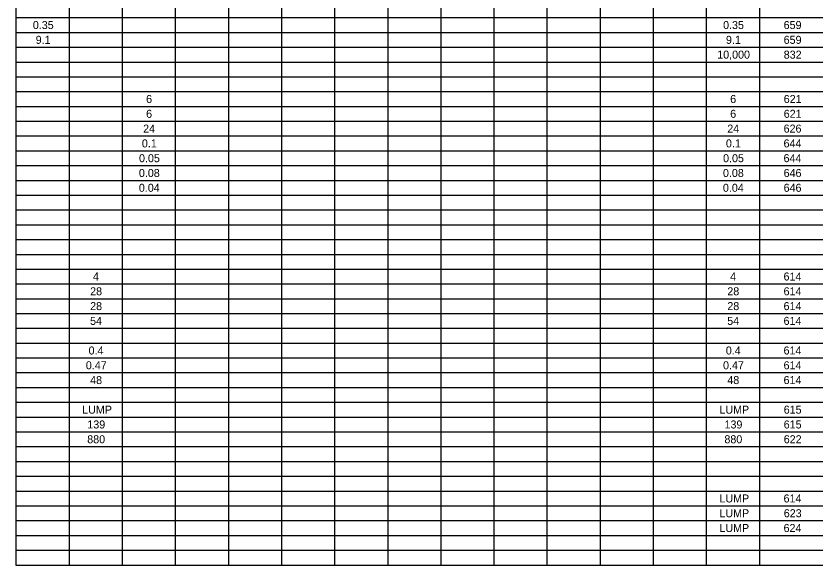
# Model space of a CAD drawing. Extents: x -98 to 34, y 0 to 58.
# Drawn here: x -97.69 to -82.55, y 36.85 to 47.24 of the extents above; entities that cross this region are included whole.
import ezdxf

# ---------------------------------------------------------------- set-up
doc = ezdxf.new("R2010")
doc.units = 0
doc.layers.add('Default', color=7, linetype='Continuous')

msp = doc.modelspace()

# ---------------------------------------------------------------- linework, layer by layer
at = {"layer": 'Default'}
for p, q in [((-97.686, 57.846), (-97.686, 36.848)), ((-84.626, 57.846), (-84.626, 36.848)), ((-83.621, 57.846), (-83.621, 36.848)), ((-96.681, 57.286), (-96.681, 36.848)), ((-95.676, 57.286), (-95.676, 36.848)), ((-94.672, 57.286), (-94.672, 36.848)), ((-93.667, 57.286), (-93.667, 36.848)), ((-92.663, 57.286), (-92.663, 36.848)), ((-91.658, 57.286), (-91.658, 36.848)), ((-90.653, 57.286), (-90.653, 36.848)), ((-89.649, 57.286), (-89.649, 36.848)), ((-88.644, 57.286), (-88.644, 36.848)), ((-87.64, 57.286), (-87.64, 36.848)), ((-86.635, 57.286), (-86.635, 36.848)), ((-85.63, 57.286), (-85.63, 36.848)), ((-97.686, 47.207), (-67.186, 47.207)), ((-97.686, 46.927), (-67.186, 46.927)), ((-97.686, 46.647), (-67.186, 46.647)), ((-97.686, 46.367), (-67.186, 46.367)), ((-97.686, 46.087), (-67.186, 46.087)), ((-97.686, 45.807), (-67.186, 45.807)), ((-97.686, 45.527), (-67.186, 45.527)), ((-97.686, 45.247), (-67.186, 45.247)), ((-97.686, 44.967), (-67.186, 44.967)), ((-97.686, 44.687), (-67.186, 44.687)), ((-97.686, 44.407), (-67.186, 44.407)), ((-97.686, 44.127), (-67.186, 44.127)), ((-97.686, 43.847), (-67.186, 43.847)), ((-97.686, 43.567), (-67.186, 43.567)), ((-97.686, 43.287), (-67.186, 43.287)), ((-97.686, 43.007), (-67.186, 43.007)), ((-97.686, 42.727), (-67.186, 42.727)), ((-97.686, 42.447), (-67.186, 42.447)), ((-97.686, 42.167), (-67.186, 42.167)), ((-97.686, 41.887), (-67.186, 41.887)), ((-97.686, 41.607), (-67.186, 41.607)), ((-97.686, 41.327), (-67.186, 41.327)), ((-97.686, 41.048), (-67.186, 41.048)), ((-97.686, 40.768), (-67.186, 40.768)), ((-97.686, 40.488), (-67.186, 40.488)), ((-97.686, 40.208), (-67.186, 40.208)), ((-97.686, 39.928), (-67.186, 39.928)), ((-97.686, 39.648), (-67.186, 39.648)), ((-97.686, 39.368), (-67.186, 39.368)), ((-97.686, 39.088), (-67.186, 39.088)), ((-97.686, 38.808), (-67.186, 38.808)), ((-97.686, 38.528), (-67.186, 38.528)), ((-97.686, 38.248), (-67.186, 38.248)), ((-97.686, 37.968), (-67.186, 37.968)), ((-97.686, 37.688), (-67.186, 37.688)), ((-97.686, 37.408), (-67.186, 37.408)), ((-97.686, 37.128), (-67.186, 37.128)), ((-97.686, 36.848), (-67.186, 36.848))]:
    msp.add_line(p, q, dxfattribs=at)

# ---------------------------------------------------------------- texts
for s, height, p in [('0.35', 0.1515, (-97.367, 46.991)), ('0.35', 0.1515, (-84.308, 46.991)), ('659', 0.1515, (-83.162, 46.991)), ('9.1', 0.1515, (-97.313, 46.711)), ('9.1', 0.1515, (-84.254, 46.711)), ('659', 0.1515, (-83.162, 46.711)), ('10,000', 0.1515, (-84.419, 46.431)), ('832', 0.1515, (-83.161, 46.431)), ('6', 0.152, (-95.224, 45.591)), ('6', 0.152, (-84.174, 45.591)), ('621', 0.1515, (-83.161, 45.591)), ('6', 0.152, (-95.224, 45.311)), ('6', 0.152, (-84.174, 45.311)), ('621', 0.1515, (-83.161, 45.311)), ('24', 0.1515, (-95.28, 45.031)), ('24', 0.1515, (-84.229, 45.031)), ('626', 0.1515, (-83.163, 45.031)), ('0.1', 0.1515, (-95.304, 44.751)), ('0.1', 0.1515, (-84.254, 44.751)), ('644', 0.1515, (-83.164, 44.751)), ('0.05', 0.1515, (-95.358, 44.471)), ('0.05', 0.1515, (-84.308, 44.471)), ('644', 0.1515, (-83.164, 44.471)), ('0.08', 0.1515, (-95.36, 44.191)), ('0.08', 0.1515, (-84.31, 44.191)), ('646', 0.1515, (-83.163, 44.191)), ('0.04', 0.1515, (-95.361, 43.911)), ('0.04', 0.1515, (-84.311, 43.911)), ('646', 0.1515, (-83.163, 43.911)), ('4', 0.152, (-96.23, 42.232)), ('4', 0.152, (-84.175, 42.232)), ('614', 0.1515, (-83.164, 42.232)), ('28', 0.1515, (-96.283, 41.952)), ('28', 0.1515, (-84.228, 41.952)), ('614', 0.1515, (-83.164, 41.952)), ('28', 0.1515, (-96.283, 41.672)), ('28', 0.1515, (-84.228, 41.672)), ('614', 0.1515, (-83.164, 41.672)), ('54', 0.1515, (-96.284, 41.392)), ('54', 0.1515, (-84.229, 41.392)), ('614', 0.1515, (-83.164, 41.392)), ('0.4', 0.1515, (-96.312, 40.832)), ('0.4', 0.1515, (-84.256, 40.832)), ('614', 0.1515, (-83.164, 40.832)), ('0.47', 0.1515, (-96.364, 40.552)), ('0.47', 0.1515, (-84.309, 40.552)), ('614', 0.1515, (-83.164, 40.552)), ('48', 0.1515, (-96.283, 40.272)), ('48', 0.1515, (-84.228, 40.272)), ('614', 0.1515, (-83.164, 40.272)), ('LUMP', 0.1515, (-96.433, 39.712)), ('LUMP', 0.1515, (-84.378, 39.712)), ('615', 0.1515, (-83.161, 39.712)), ('139', 0.1515, (-96.336, 39.432)), ('139', 0.1515, (-84.281, 39.432)), ('615', 0.1515, (-83.161, 39.432)), ('880', 0.1515, (-96.338, 39.152)), ('880', 0.1515, (-84.283, 39.152)), ('622', 0.1515, (-83.161, 39.152)), ('LUMP', 0.1515, (-84.378, 38.032)), ('614', 0.1515, (-83.164, 38.032)), ('LUMP', 0.1515, (-84.378, 37.752)), ('623', 0.1515, (-83.16, 37.752)), ('LUMP', 0.1515, (-84.378, 37.472)), ('624', 0.1515, (-83.164, 37.472))]:
    msp.add_text(s, height=height, dxfattribs=at).set_placement(p)

doc.saveas('drawing.dxf')
